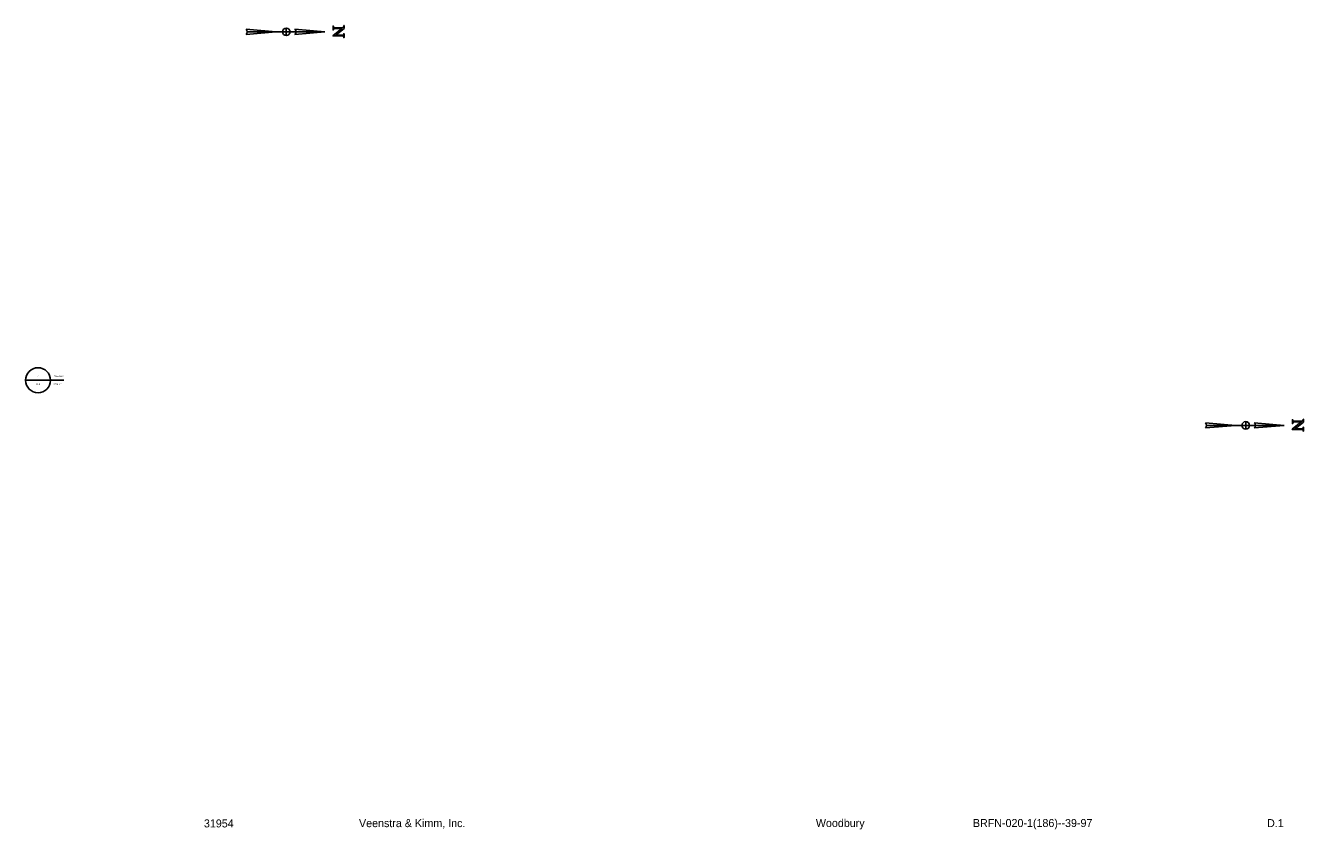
# Model space of a CAD drawing. Extents: x -0.16 to 2.5, y 0.07 to 1.75.
import ezdxf

# ---------------------------------------------------------------- set-up
doc = ezdxf.new("R2010")
doc.units = 0
for name, color, linetype in [('Default', 7, 'Continuous'), ('SheetGridMinor', 7, 'Continuous'), ('SheetText', 7, 'Continuous')]:
    doc.layers.add(name, color=color, linetype=linetype)

msp = doc.modelspace()

# ---------------------------------------------------------------- linework, layer by layer
at = {"layer": 'Default'}
for p, q in [((-0.1623, 1.0094), (-0.1102, 1.0094)), ((-0.136, 1.0094), (-0.0826, 1.0094))]:
    msp.add_line(p, q, dxfattribs=at)
msp.add_circle((-0.1363, 1.0094), 0.026, dxfattribs=at)
at = {"layer": 'SheetGridMinor'}
for p, q in [((0.3592, 1.7352), (0.297, 1.7406)), ((0.3592, 1.7352), (0.297, 1.7297)), ((0.2992, 1.7352), (0.3592, 1.7352)), ((0.2992, 1.7352), (0.461, 1.7352)), ((0.373, 1.7352), (0.3808, 1.7352)), ((0.3808, 1.7352), (0.3808, 1.743)), ((0.3808, 1.7274), (0.3808, 1.743)), ((0.3808, 1.7274), (0.3808, 1.7352)), ((0.3808, 1.7352), (0.3886, 1.7352)), ((0.461, 1.7352), (0.3988, 1.7406)), ((0.461, 1.7352), (0.3988, 1.7297)), ((0.401, 1.7352), (0.4011, 1.7352)), ((0.4011, 1.7352), (0.461, 1.7352)), ((2.3575, 0.9153), (2.2952, 0.9207)), ((2.3575, 0.9153), (2.2952, 0.9099)), ((2.2974, 0.9153), (2.3575, 0.9153)), ((2.2974, 0.9153), (2.4593, 0.9153)), ((2.3713, 0.9153), (2.3791, 0.9153)), ((2.3791, 0.9153), (2.3791, 0.9231)), ((2.3791, 0.9075), (2.3791, 0.9231)), ((2.3791, 0.9075), (2.3791, 0.9153)), ((2.3791, 0.9153), (2.3869, 0.9153)), ((2.4593, 0.9153), (2.397, 0.9207)), ((2.4593, 0.9153), (2.397, 0.9099)), ((2.3992, 0.9153), (2.3994, 0.9153)), ((2.3994, 0.9153), (2.4593, 0.9153))]:
    msp.add_line(p, q, dxfattribs=at)
for points in [[(0.4971, 1.7265), (0.4778, 1.7265), (0.4778, 1.7271), (0.4963, 1.7422), (0.4821, 1.7422)], [(0.4788, 1.7398), (0.4788, 1.739), (0.4782, 1.739), (0.4782, 1.747), (0.4788, 1.747), (0.4788, 1.7462)], [(0.4821, 1.7437), (0.4981, 1.7437)], [(0.5011, 1.7482), (0.5011, 1.7421), (0.4839, 1.728), (0.4971, 1.728)], [(0.5005, 1.7482), (0.5011, 1.7482)], [(0.5005, 1.7305), (0.5005, 1.7313), (0.5011, 1.7313), (0.5011, 1.7233), (0.5005, 1.7233), (0.5005, 1.7241)], [(2.4954, 0.9067), (2.476, 0.9067), (2.476, 0.9073), (2.4945, 0.9224), (2.4804, 0.9224)], [(2.477, 0.9199), (2.477, 0.9191), (2.4764, 0.9191), (2.4764, 0.9271), (2.477, 0.9271), (2.477, 0.9263)], [(2.4804, 0.9238), (2.4963, 0.9238)], [(2.4993, 0.9284), (2.4993, 0.9222), (2.4821, 0.9081), (2.4954, 0.9081)], [(2.4987, 0.9284), (2.4993, 0.9284)], [(2.4987, 0.9106), (2.4987, 0.9114), (2.4993, 0.9114), (2.4993, 0.9034), (2.4987, 0.9034), (2.4987, 0.9042)]]:
    msp.add_lwpolyline(points, dxfattribs=at)
for centre, start, end in [((0.2914, 1.7352), 315.7867, 44.2134), ((0.2914, 1.7352), 315.7867, 360), ((0.3808, 1.7352), 360, 359.4464), ((0.3808, 1.7352), 90, 180), ((0.3808, 1.7352), 270, 359.9989), ((0.3932, 1.7352), 315.7867, 44.2133), ((0.3932, 1.7352), 360, 44.2134), ((2.2896, 0.9153), 315.7867, 44.2134), ((2.2896, 0.9153), 315.7867, 360), ((2.3791, 0.9153), 360, 359.4464), ((2.3791, 0.9153), 90, 180), ((2.3791, 0.9153), 270, 359.9989), ((2.3914, 0.9153), 315.7867, 44.2133), ((2.3914, 0.9153), 360, 44.2134)]:
    msp.add_arc(centre, 0.00781, start, end, dxfattribs=at)
for points in [[(0.4788, 1.7462), (0.4788, 1.7447), (0.4797, 1.7441), (0.4802, 1.7437), (0.4821, 1.7437)], [(0.4821, 1.7422), (0.48, 1.7422), (0.4795, 1.7418), (0.4788, 1.7412), (0.4788, 1.7398)], [(0.4971, 1.728), (0.4992, 1.728), (0.4998, 1.7285), (0.5005, 1.7291), (0.5005, 1.7305)], [(0.4981, 1.7437), (0.4992, 1.7447), (0.4996, 1.7452), (0.5, 1.7458), (0.5003, 1.7468), (0.5005, 1.7472), (0.5005, 1.7482)], [(0.5005, 1.7241), (0.5005, 1.7256), (0.4996, 1.7262), (0.499, 1.7265), (0.4971, 1.7265)], [(2.477, 0.9263), (2.477, 0.9248), (2.4779, 0.9242), (2.4785, 0.9238), (2.4804, 0.9238)], [(2.4804, 0.9224), (2.4783, 0.9224), (2.4777, 0.9219), (2.477, 0.9213), (2.477, 0.9199)], [(2.4954, 0.9081), (2.4975, 0.9081), (2.498, 0.9086), (2.4987, 0.9092), (2.4987, 0.9106)], [(2.4987, 0.9042), (2.4987, 0.9057), (2.4978, 0.9063), (2.4973, 0.9067), (2.4954, 0.9067)], [(2.4963, 0.9238), (2.4975, 0.9248), (2.4979, 0.9254), (2.4982, 0.9259), (2.4986, 0.9269), (2.4987, 0.9274), (2.4987, 0.9284)]]:
    msp.add_open_spline(points, degree=3, dxfattribs=at)

# ---------------------------------------------------------------- texts
at = {"layer": 'Default'}
for s, p in [('4', (-0.1374, 1.016)), ('Drawing-3', (-0.1037, 1.016)), ('D.1', (-0.1392, 0.9996)), ('6"=1\'-0"', (-0.1037, 0.9996))]:
    msp.add_text(s, height=0.00328, dxfattribs=at).set_placement(p)
at = {"layer": 'SheetText'}
for s, height, p in [('31954', 0.01667, (0.2092, 0.0777)), ('Veenstra & Kimm, Inc.', 0.016667, (0.5322, 0.0783)), ('Woodbury', 0.01667, (1.4838, 0.0785)), ('BRFN-020-1(186)--39-97', 0.016667, (1.8108, 0.0785)), ('D.1', 0.01667, (2.4236, 0.0783))]:
    msp.add_text(s, height=height, dxfattribs=at).set_placement(p)

doc.saveas('drawing.dxf')
